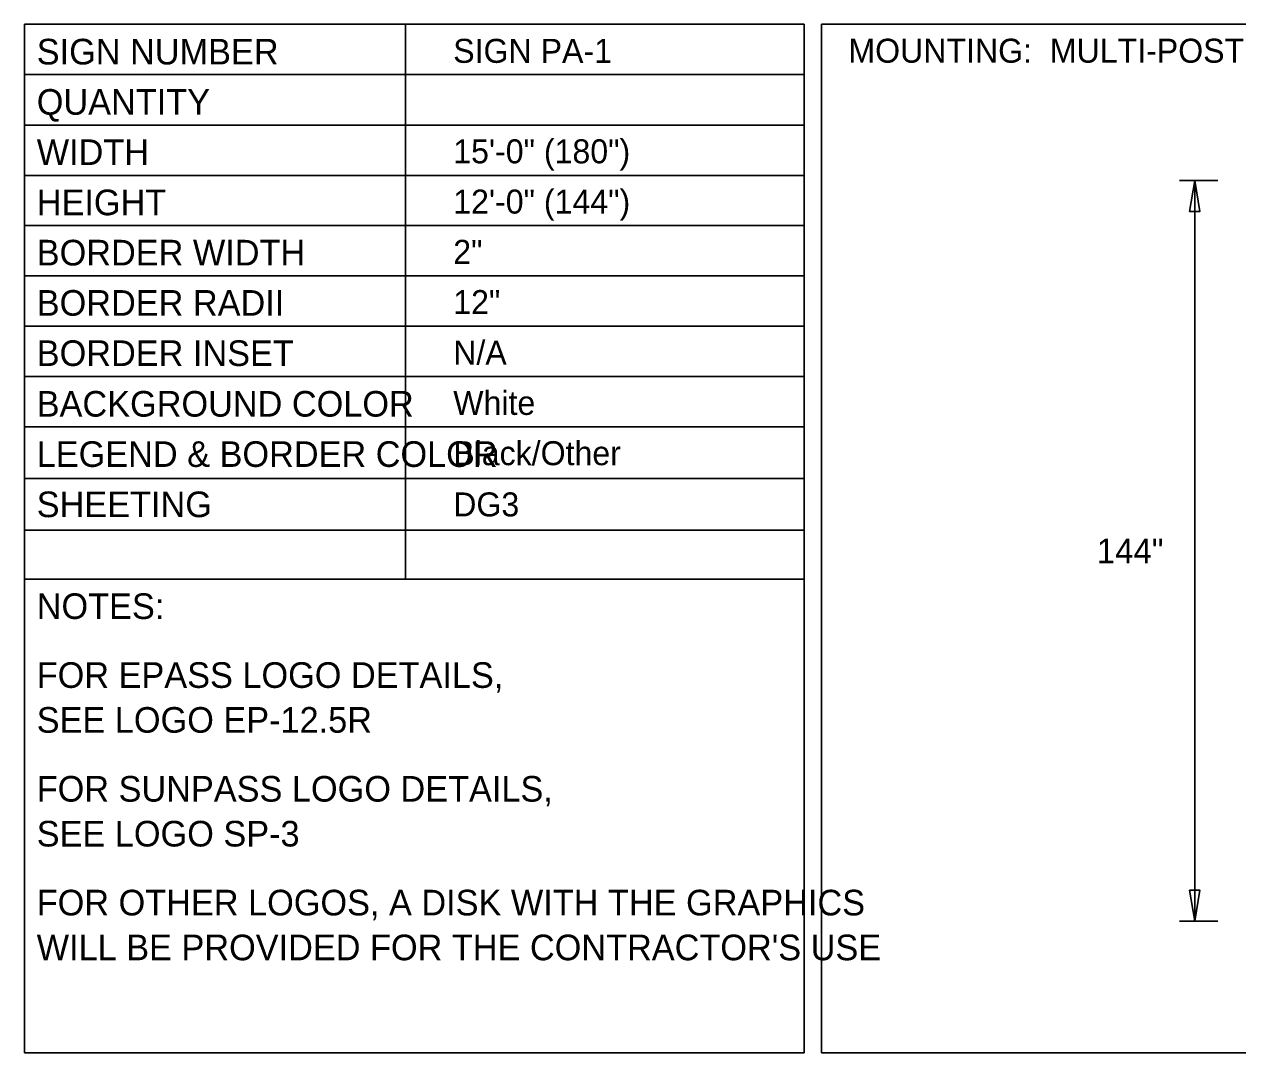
# Model space of a CAD drawing. Extents: x 10268259 to 10268554, y 2141099 to 2141249.
# Drawn here: x 10268318.48 to 10268353.87, y 2141173.53 to 2141203.53 of the extents above; entities that cross this region are included whole.
import ezdxf

# ---------------------------------------------------------------- set-up
doc = ezdxf.new("R2010")
doc.units = 0
for name, color, linetype in [('60', 7, 'Continuous'), ('62', 7, 'Continuous'), ('GSDims', 7, 'Continuous'), ('TextMisc', 7, 'Continuous')]:
    doc.layers.add(name, color=color, linetype=linetype)

msp = doc.modelspace()

# ---------------------------------------------------------------- linework, layer by layer
at = {"layer": '60'}
for p, q in [((10268318.48, 2141203.528), (10268318.48, 2141173.528)), ((10268318.48, 2141203.528), (10268341.23, 2141203.528)), ((10268329.598, 2141203.525), (10268329.598, 2141187.342)), ((10268341.23, 2141203.528), (10268341.23, 2141173.528)), ((10268341.73, 2141203.528), (10268341.73, 2141173.528)), ((10268341.73, 2141203.528), (10268393.98, 2141203.528)), ((10268318.48, 2141202.063), (10268341.23, 2141202.063)), ((10268318.48, 2141200.587), (10268341.23, 2141200.587)), ((10268318.48, 2141199.121), (10268341.23, 2141199.121)), ((10268318.48, 2141197.655), (10268341.23, 2141197.655)), ((10268318.48, 2141196.19), (10268341.23, 2141196.19)), ((10268318.48, 2141194.724), (10268341.23, 2141194.724)), ((10268318.48, 2141193.258), (10268341.23, 2141193.258)), ((10268318.48, 2141191.783), (10268341.23, 2141191.783)), ((10268318.48, 2141190.278), (10268341.23, 2141190.278)), ((10268318.48, 2141188.773), (10268341.23, 2141188.773)), ((10268318.478, 2141187.342), (10268341.229, 2141187.342)), ((10268318.48, 2141173.528), (10268341.23, 2141173.528)), ((10268341.73, 2141173.528), (10268393.98, 2141173.528))]:
    msp.add_line(p, q, dxfattribs=at)
at = {"layer": 'GSDims'}
for p, q in [((10268353.295, 2141198.968), (10268352.17, 2141198.968)), ((10268352.62, 2141177.367), (10268352.62, 2141198.968)), ((10268353.295, 2141177.367), (10268352.17, 2141177.367))]:
    msp.add_line(p, q, dxfattribs=at)
for points in [[(10268352.62, 2141198.968), (10268352.77, 2141198.068), (10268352.47, 2141198.068)], [(10268352.62, 2141177.367), (10268352.77, 2141178.267), (10268352.47, 2141178.267)]]:
    msp.add_lwpolyline(points, close=True, dxfattribs=at)

# ---------------------------------------------------------------- texts
at = {"layer": '62'}
for s, p in [('SIGN PA-1', (10268330.99, 2141202.403)), ('MOUNTING:  MULTI-POST GROUND MOUNT (GM-X)', (10268342.516, 2141202.407)), ('15\'-0" (180")', (10268330.99, 2141199.472)), ('12\'-0" (144")', (10268330.99, 2141198.006)), ('2"', (10268330.99, 2141196.54)), ('12"', (10268330.99, 2141195.074)), ('N/A', (10268330.99, 2141193.599)), ('White', (10268330.99, 2141192.133)), ('Black/Other', (10268330.99, 2141190.667)), ('DG3', (10268330.99, 2141189.173))]:
    msp.add_text(s, height=0.7, dxfattribs=at).set_placement(p)
at = {"layer": 'GSDims'}
msp.add_text('144"', height=0.72, dxfattribs=at).set_placement((10268349.759, 2141187.807))
at = {"layer": 'TextMisc'}
for s, height, p in [('SIGN NUMBER', 0.74756, (10268318.842, 2141202.356)), ('QUANTITY', 0.7476, (10268318.842, 2141200.89)), ('WIDTH', 0.7476, (10268318.842, 2141199.424)), ('HEIGHT', 0.7476, (10268318.842, 2141197.958)), ('BORDER WIDTH', 0.74756, (10268318.842, 2141196.493)), ('BORDER RADII', 0.74756, (10268318.842, 2141195.027)), ('BORDER INSET', 0.74756, (10268318.842, 2141193.561)), ('BACKGROUND COLOR', 0.74756, (10268318.841, 2141192.083)), ('LEGEND & BORDER COLOR', 0.74756, (10268318.841, 2141190.617)), ('SHEETING', 0.7476, (10268318.841, 2141189.151)), ('NOTES:', 0.7476, (10268318.841, 2141186.181)), ('FOR EPASS LOGO DETAILS,', 0.74756, (10268318.841, 2141184.171)), ('SEE LOGO EP-12.5R', 0.74756, (10268318.841, 2141182.863)), ('FOR SUNPASS LOGO DETAILS,', 0.74756, (10268318.841, 2141180.853)), ('SEE LOGO SP-3', 0.74756, (10268318.841, 2141179.544)), ('FOR OTHER LOGOS, A DISK WITH THE GRAPHICS', 0.74756, (10268318.841, 2141177.534)), ("WILL BE PROVIDED FOR THE CONTRACTOR'S USE", 0.74756, (10268318.841, 2141176.226))]:
    msp.add_text(s, height=height, dxfattribs=at).set_placement(p)

doc.saveas('drawing.dxf')
